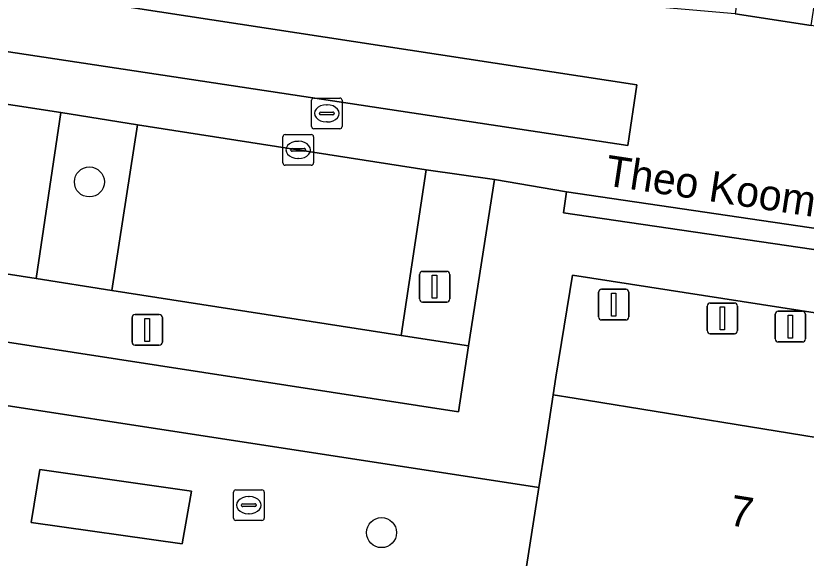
# Model space of a CAD drawing. Extents: x 161090 to 161692, y 379509 to 380907.
# Drawn here: x 161316.51 to 161342.3, y 380460.02 to 380477.71 of the extents above; entities that cross this region are included whole.
import ezdxf

# ---------------------------------------------------------------- set-up
doc = ezdxf.new("R2010")
doc.units = 0
for name, color, linetype in [('IMGEO_Afsluitpaal', 7, 'Continuous'), ('IMGEO_Boom', 7, 'Continuous'), ('IMGEO_Brandkraan', 7, 'Continuous'), ('IMGEO_Groenvoorziening', 7, 'Continuous'), ('IMGEO_Kolk', 7, 'Continuous'), ('IMGEO_Lichtmast', 7, 'Continuous'), ('IMGEO_Openbare_ruimte_label', 7, 'Continuous'), ('IMGEO_Pand', 7, 'Continuous'), ('IMGEO_Pand_nummerreeks', 7, 'Continuous'), ('IMGEO_Parkeervlak_open', 7, 'Continuous'), ('IMGEO_Rijbaan_lokaal_gesloten', 7, 'Continuous'), ('IMGEO_Rijbaan_lokaal_halfverhard', 7, 'Continuous'), ('IMGEO_Rijbaan_lokaal_open', 7, 'Continuous'), ('IMGEO_Rioolput', 7, 'Continuous'), ('IMGEO_Voetpad_gesloten', 7, 'Continuous')]:
    doc.layers.add(name, color=color, linetype=linetype)

msp = doc.modelspace()

# ---------------------------------------------------------------- linework, layer by layer
at = {"layer": 'IMGEO_Afsluitpaal'}
for p, q in [((161335.527, 380467.894), (161335.527, 380468.694)), ((161335.527, 380468.694), (161335.527, 380467.894)), ((161335.627, 380468.794), (161336.417, 380468.794)), ((161336.417, 380468.794), (161335.627, 380468.794)), ((161336.517, 380468.694), (161336.517, 380467.894)), ((161336.517, 380467.894), (161336.517, 380468.694)), ((161341.291, 380467.177), (161341.291, 380467.977)), ((161341.291, 380467.977), (161341.291, 380467.177)), ((161341.391, 380468.077), (161342.181, 380468.077)), ((161342.181, 380468.077), (161341.391, 380468.077)), ((161342.281, 380467.977), (161342.281, 380467.177)), ((161342.281, 380467.177), (161342.281, 380467.977)), ((161336.417, 380467.794), (161335.627, 380467.794)), ((161335.627, 380467.794), (161336.417, 380467.794)), ((161342.181, 380467.077), (161341.391, 380467.077)), ((161341.391, 380467.077), (161342.181, 380467.077))]:
    msp.add_line(p, q, dxfattribs=at)
for points in [[(161335.947, 380468.669), (161336.097, 380468.669), (161336.097, 380467.919), (161335.947, 380467.919), (161335.947, 380468.669)], [(161341.711, 380467.952), (161341.861, 380467.952), (161341.861, 380467.202), (161341.711, 380467.202), (161341.711, 380467.952)]]:
    msp.add_lwpolyline(points, dxfattribs=at)
for centre, start, end in [((161335.627, 380468.694), 90, 180), ((161335.627, 380468.694), 90, 180), ((161336.417, 380468.694), 0, 90), ((161336.417, 380468.694), 360, 90), ((161341.391, 380467.977), 90, 180), ((161341.391, 380467.977), 90, 180), ((161342.181, 380467.977), 0, 90), ((161342.181, 380467.977), 360, 90), ((161335.627, 380467.894), 180, 270), ((161335.627, 380467.894), 180, 270), ((161336.417, 380467.894), 270, 0), ((161336.417, 380467.894), 270, 0), ((161341.391, 380467.177), 180, 270), ((161341.391, 380467.177), 180, 270), ((161342.181, 380467.177), 270, 0), ((161342.181, 380467.177), 270, 0)]:
    msp.add_arc(centre, 0.1, start, end, dxfattribs=at)
at = {"layer": 'IMGEO_Boom'}
for centre in [(161318.913, 380472.294), (161328.447, 380460.856)]:
    msp.add_circle(centre, 0.489, dxfattribs=at)
at = {"layer": 'IMGEO_Brandkraan'}
for p, q in [((161323.692, 380462.253), (161324.544, 380462.253)), ((161323.617, 380461.327), (161323.617, 380462.179)), ((161324.105, 380462.033), (161324.13, 380462.033)), ((161324.618, 380462.179), (161324.618, 380461.327)), ((161323.876, 380461.747), (161323.876, 380461.759)), ((161323.919, 380461.796), (161324.317, 380461.796)), ((161324.36, 380461.759), (161324.36, 380461.747)), ((161324.314, 380461.71), (161323.916, 380461.71)), ((161324.128, 380461.473), (161324.103, 380461.473)), ((161324.544, 380461.253), (161323.692, 380461.253))]:
    msp.add_line(p, q, dxfattribs=at)
for points in [[(161323.692, 380462.253), (161324.544, 380462.253)], [(161323.617, 380461.327), (161323.617, 380462.179)], [(161324.618, 380462.179), (161324.618, 380461.327)], [(161324.544, 380461.253), (161323.692, 380461.253)]]:
    msp.add_lwpolyline(points, dxfattribs=at)
for centre, radius, start, end in [((161323.694, 380462.177), 0.0765, 91.552, 178.448), ((161323.694, 380462.177), 0.0765, 91.552, 178.448), ((161324.542, 380462.177), 0.0765, 1.552, 88.448), ((161324.542, 380462.177), 0.0765, 1.552, 88.448), ((161323.916, 380461.756), 0.0403, 85.8775, 175.7526), ((161323.913, 380461.746), 0.0366, 178.938, 274.7102), ((161324.317, 380461.753), 0.043, 264.8664, 352.4533), ((161324.321, 380461.758), 0.0386, 1.7309, 96.639), ((161323.694, 380461.329), 0.0765, 181.552, 268.448), ((161323.694, 380461.329), 0.0765, 181.552, 268.448), ((161324.542, 380461.329), 0.0765, 271.552, 358.448), ((161324.542, 380461.329), 0.0765, 271.552, 358.448)]:
    msp.add_arc(centre, radius, start, end, dxfattribs=at)
for centre, major_axis, ratio, start_param, end_param in [((161324.104, 380461.753), (-0.387, 0.002), 0.722429, 4.712389, 7.853982), ((161324.129, 380461.753), (-0.39, 0.002), 0.717154, 1.570796, 4.712389)]:
    msp.add_ellipse(centre, major_axis=major_axis, ratio=ratio, start_param=start_param, end_param=end_param, dxfattribs=at)
at = {"layer": 'IMGEO_Groenvoorziening'}
for points in [[(161320.483, 380474.154), (161317.985, 380474.559), (161317.177, 380469.145), (161319.647, 380468.755)], [(161332.128, 380472.377), (161329.904, 380472.69), (161329.093, 380467.287), (161331.289, 380466.946)], [(161317.177, 380469.145), (161310.029, 380470.251), (161307.533, 380470.637), (161300.574, 380471.68), (161300.239, 380469.535), (161330.957, 380464.795), (161331.289, 380466.946), (161329.093, 380467.287), (161319.647, 380468.755)], [(161334.13, 380465.931), (161334.051, 380465.355), (161334.728, 380465.245), (161347.044, 380463.247), (161347.648, 380467.248), (161334.684, 380469.253)], [(161333.579, 380462.328), (161304.447, 380466.803), (161303.211, 380459.226), (161345.91, 380452.696), (161344.888, 380445.59), (161345.748, 380445.468), (161345.355, 380442.905), (161346.314, 380442.765), (161348.083, 380442.507), (161348.425, 380442.457), (161349.861, 380451.744), (161348.112, 380452.012), (161348.085, 380451.838), (161347.76, 380451.888), (161347.883, 380452.692), (161332.452, 380455.091)], [(161322.243, 380462.204), (161317.301, 380462.921), (161317.018, 380461.188), (161321.945, 380460.494)], [(161317.018, 380461.188), (161317.301, 380462.921), (161322.243, 380462.204), (161321.945, 380460.494)]]:
    msp.add_lwpolyline(points, close=True, dxfattribs=at)
at = {"layer": 'IMGEO_Kolk'}
for p, q in [((161325.303, 380473.839), (161326.155, 380473.839)), ((161325.228, 380472.913), (161325.228, 380473.765)), ((161325.716, 380473.619), (161325.741, 380473.619)), ((161326.229, 380473.765), (161326.229, 380472.913)), ((161325.487, 380473.333), (161325.487, 380473.345)), ((161325.53, 380473.382), (161325.928, 380473.382)), ((161325.971, 380473.345), (161325.971, 380473.333)), ((161325.925, 380473.296), (161325.527, 380473.296)), ((161326.155, 380472.839), (161325.303, 380472.839)), ((161325.739, 380473.059), (161325.714, 380473.059))]:
    msp.add_line(p, q, dxfattribs=at)
for points in [[(161325.303, 380473.839), (161326.155, 380473.839)], [(161325.228, 380472.913), (161325.228, 380473.765)], [(161326.229, 380473.765), (161326.229, 380472.913)], [(161326.155, 380472.839), (161325.303, 380472.839)]]:
    msp.add_lwpolyline(points, dxfattribs=at)
for centre, radius, start, end in [((161325.305, 380473.763), 0.0765, 91.552, 178.448), ((161325.305, 380473.763), 0.0765, 91.552, 178.448), ((161326.153, 380473.763), 0.0765, 1.552, 88.448), ((161326.153, 380473.763), 0.0765, 1.552, 88.448), ((161325.527, 380473.342), 0.0403, 85.8775, 175.7526), ((161325.524, 380473.332), 0.0366, 178.938, 274.7102), ((161325.928, 380473.339), 0.043, 264.8664, 352.4533), ((161325.932, 380473.344), 0.0386, 1.7309, 96.639), ((161325.305, 380472.915), 0.0765, 181.552, 268.448), ((161325.305, 380472.915), 0.0765, 181.552, 268.448), ((161326.153, 380472.915), 0.0765, 271.552, 358.448), ((161326.153, 380472.915), 0.0765, 271.552, 358.448)]:
    msp.add_arc(centre, radius, start, end, dxfattribs=at)
for centre, major_axis, ratio, start_param, end_param in [((161325.715, 380473.339), (-0.387, 0.002), 0.722429, 4.712389, 7.853982), ((161325.74, 380473.339), (-0.39, 0.002), 0.717154, 1.570796, 4.712389)]:
    msp.add_ellipse(centre, major_axis=major_axis, ratio=ratio, start_param=start_param, end_param=end_param, dxfattribs=at)
at = {"layer": 'IMGEO_Lichtmast'}
for p, q in [((161329.684, 380468.477), (161329.684, 380469.277)), ((161329.684, 380469.277), (161329.684, 380468.477)), ((161329.784, 380469.377), (161330.574, 380469.377)), ((161330.574, 380469.377), (161329.784, 380469.377)), ((161330.674, 380469.277), (161330.674, 380468.477)), ((161330.674, 380468.477), (161330.674, 380469.277)), ((161330.574, 380468.377), (161329.784, 380468.377)), ((161329.784, 380468.377), (161330.574, 380468.377)), ((161339.074, 380467.445), (161339.074, 380468.245)), ((161339.074, 380468.245), (161339.074, 380467.445)), ((161339.174, 380468.345), (161339.964, 380468.345)), ((161339.964, 380468.345), (161339.174, 380468.345)), ((161340.064, 380468.245), (161340.064, 380467.445)), ((161340.064, 380467.445), (161340.064, 380468.245)), ((161320.405, 380467.97), (161321.195, 380467.97)), ((161321.195, 380467.97), (161320.405, 380467.97)), ((161320.305, 380467.07), (161320.305, 380467.87)), ((161320.305, 380467.87), (161320.305, 380467.07)), ((161321.295, 380467.87), (161321.295, 380467.07)), ((161321.295, 380467.07), (161321.295, 380467.87)), ((161339.964, 380467.345), (161339.174, 380467.345)), ((161339.174, 380467.345), (161339.964, 380467.345)), ((161321.195, 380466.97), (161320.405, 380466.97)), ((161320.405, 380466.97), (161321.195, 380466.97))]:
    msp.add_line(p, q, dxfattribs=at)
for points in [[(161330.104, 380469.252), (161330.254, 380469.252), (161330.254, 380468.502), (161330.104, 380468.502), (161330.104, 380469.252)], [(161339.494, 380468.22), (161339.644, 380468.22), (161339.644, 380467.47), (161339.494, 380467.47), (161339.494, 380468.22)], [(161320.725, 380467.845), (161320.875, 380467.845), (161320.875, 380467.095), (161320.725, 380467.095), (161320.725, 380467.845)]]:
    msp.add_lwpolyline(points, dxfattribs=at)
for centre, start, end in [((161329.784, 380469.277), 90, 180), ((161329.784, 380469.277), 90, 180), ((161330.574, 380469.277), 0, 90), ((161330.574, 380469.277), 360, 90), ((161329.784, 380468.477), 180, 270), ((161329.784, 380468.477), 180, 270), ((161330.574, 380468.477), 270, 0), ((161330.574, 380468.477), 270, 0), ((161339.174, 380468.245), 90, 180), ((161339.174, 380468.245), 90, 180), ((161339.964, 380468.245), 0, 90), ((161339.964, 380468.245), 360, 90), ((161320.405, 380467.87), 90, 180), ((161320.405, 380467.87), 90, 180), ((161321.195, 380467.87), 0, 90), ((161321.195, 380467.87), 360, 90), ((161339.174, 380467.445), 180, 270), ((161339.174, 380467.445), 180, 270), ((161339.964, 380467.445), 270, 0), ((161339.964, 380467.445), 270, 0), ((161320.405, 380467.07), 180, 270), ((161320.405, 380467.07), 180, 270), ((161321.195, 380467.07), 270, 0), ((161321.195, 380467.07), 270, 0)]:
    msp.add_arc(centre, 0.1, start, end, dxfattribs=at)
at = {"layer": 'IMGEO_Pand'}
msp.add_lwpolyline([(161346.381, 380459.061), (161347.044, 380463.247), (161334.728, 380465.245), (161334.051, 380465.355), (161333.782, 380463.629), (161333.579, 380462.328), (161332.452, 380455.091), (161347.883, 380452.692), (161347.76, 380451.888), (161348.085, 380451.838), (161348.112, 380452.012), (161349.861, 380451.744), (161350.243, 380451.685), (161352.388, 380451.356), (161352.429, 380451.626), (161352.165, 380451.666), (161353.228, 380458.595), (161352.991, 380458.631), (161352.968, 380458.48), (161350.923, 380458.794), (161348.802, 380459.119), (161348.497, 380459.166), (161348.432, 380458.747)], close=True, dxfattribs=at)
at = {"layer": 'IMGEO_Parkeervlak_open'}
for points in [[(161310.805, 380475.658), (161310.029, 380470.251), (161317.177, 380469.145), (161317.985, 380474.559)], [(161329.904, 380472.69), (161320.483, 380474.154), (161319.647, 380468.755), (161329.093, 380467.287)]]:
    msp.add_lwpolyline(points, close=True, dxfattribs=at)
at = {"layer": 'IMGEO_Rijbaan_lokaal_gesloten'}
msp.add_lwpolyline([(161336.484, 380473.48), (161285.911, 380481.132), (161278.697, 380482.355), (161219.62, 380491.428), (161219.91, 380493.339), (161336.783, 380475.457)], close=True, dxfattribs=at)
for points in [[(161288.088, 380479.111), (161295.31, 380478.007), (161296.487, 380477.82), (161301.347, 380477.091), (161308.397, 380476.013), (161310.805, 380475.658), (161317.985, 380474.559), (161320.483, 380474.154), (161329.904, 380472.69), (161332.128, 380472.377), (161334.483, 380471.977), (161352.537, 380469.322)], [(161346.509, 380476.771), (161342.463, 380477.394), (161339.984, 380477.773), (161335.342, 380478.178)]]:
    msp.add_lwpolyline(points, dxfattribs=at)
at = {"layer": 'IMGEO_Rijbaan_lokaal_halfverhard'}
for points in [[(161334.483, 380471.977), (161334.385, 380471.286), (161352.358, 380468.658)], [(161352.537, 380469.322), (161334.483, 380471.977)]]:
    msp.add_lwpolyline(points, dxfattribs=at)
at = {"layer": 'IMGEO_Rijbaan_lokaal_open'}
for points in [[(161388.922, 380797.51), (161375.194, 380708.235), (161339.984, 380477.773), (161342.463, 380477.394), (161377.702, 380708.239), (161391.386, 380797.079), (161398.722, 380843.492), (161399.153, 380846.596), (161398.722, 380846.664), (161396.663, 380846.991), (161396.234, 380843.996)], [(161219.62, 380491.428), (161278.697, 380482.355), (161285.911, 380481.132), (161336.484, 380473.48), (161336.783, 380475.457), (161219.91, 380493.339)]]:
    msp.add_lwpolyline(points, close=True, dxfattribs=at)
at = {"layer": 'IMGEO_Rioolput'}
for p, q in [((161326.161, 380474.104), (161326.161, 380474.956)), ((161326.236, 380475.03), (161327.088, 380475.03)), ((161327.162, 380474.956), (161327.162, 380474.104)), ((161326.649, 380474.81), (161326.674, 380474.81)), ((161326.42, 380474.524), (161326.42, 380474.536)), ((161326.858, 380474.487), (161326.46, 380474.487)), ((161326.463, 380474.573), (161326.861, 380474.573)), ((161326.904, 380474.536), (161326.904, 380474.524)), ((161326.672, 380474.25), (161326.647, 380474.25)), ((161327.088, 380474.03), (161326.236, 380474.03))]:
    msp.add_line(p, q, dxfattribs=at)
for points in [[(161326.161, 380474.104), (161326.161, 380474.956)], [(161326.236, 380475.03), (161327.088, 380475.03)], [(161327.162, 380474.956), (161327.162, 380474.104)], [(161327.088, 380474.03), (161326.236, 380474.03)]]:
    msp.add_lwpolyline(points, dxfattribs=at)
for centre, radius, start, end in [((161326.238, 380474.954), 0.0765, 91.552, 178.448), ((161326.238, 380474.954), 0.0765, 91.552, 178.448), ((161327.086, 380474.954), 0.0765, 1.552, 88.448), ((161327.086, 380474.954), 0.0765, 1.552, 88.448), ((161326.46, 380474.533), 0.0403, 85.8775, 175.7526), ((161326.457, 380474.523), 0.0366, 178.938, 274.7102), ((161326.861, 380474.53), 0.043, 264.8664, 352.4533), ((161326.865, 380474.535), 0.0386, 1.7309, 96.639), ((161326.238, 380474.106), 0.0765, 181.552, 268.448), ((161326.238, 380474.106), 0.0765, 181.552, 268.448), ((161327.086, 380474.106), 0.0765, 271.552, 358.448), ((161327.086, 380474.106), 0.0765, 271.552, 358.448)]:
    msp.add_arc(centre, radius, start, end, dxfattribs=at)
for centre, major_axis, ratio, start_param, end_param in [((161326.648, 380474.53), (-0.387, 0.002), 0.722429, 4.712389, 7.853982), ((161326.673, 380474.53), (-0.39, 0.002), 0.717154, 1.570796, 4.712389)]:
    msp.add_ellipse(centre, major_axis=major_axis, ratio=ratio, start_param=start_param, end_param=end_param, dxfattribs=at)
at = {"layer": 'IMGEO_Voetpad_gesloten'}
for points in [[(161351.72, 380465.058), (161352.358, 380468.658), (161334.385, 380471.286), (161334.483, 380471.977), (161332.128, 380472.377), (161331.289, 380466.946), (161330.957, 380464.795), (161300.239, 380469.535), (161300.574, 380471.68), (161301.347, 380477.091), (161296.487, 380477.82), (161295.671, 380472.434), (161295.347, 380470.3), (161218.355, 380482.088)], [(161218.136, 380480.015), (161289.794, 380468.952), (161294.974, 380468.152), (161299.94, 380467.397), (161301.017, 380467.33), (161304.447, 380466.803), (161333.579, 380462.328), (161333.782, 380463.629), (161334.051, 380465.355), (161334.13, 380465.931), (161334.684, 380469.253), (161347.648, 380467.248), (161349.762, 380466.921), (161349.094, 380462.499), (161351.489, 380462.107), (161356.996, 380461.235), (161357.571, 380461.128), (161357.736, 380462.181), (161357.904, 380463.25), (161356.982, 380463.387), (161352.383, 380464.161)]]:
    msp.add_lwpolyline(points, dxfattribs=at)

# ---------------------------------------------------------------- texts
at = {"layer": 'IMGEO_Openbare_ruimte_label'}
msp.add_text('Theo Koomenlaan', height=1, rotation=351.3758, dxfattribs=at).set_placement((161335.704, 380472.189))
at = {"layer": 'IMGEO_Pand_nummerreeks'}
msp.add_text('7', height=1, rotation=350.7868, dxfattribs=at).set_placement((161339.751, 380461.108))

doc.saveas('drawing.dxf')
